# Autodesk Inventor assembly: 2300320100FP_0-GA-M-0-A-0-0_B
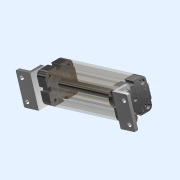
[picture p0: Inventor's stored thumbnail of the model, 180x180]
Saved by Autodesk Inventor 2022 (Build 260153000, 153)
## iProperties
Category: PARTsolutions
Company: METALWORK
Part Number: 2300320100FP_0-GA-M-0-A-0-0_B
Catalog Web Link: www.cadenas.de
Description: Compact cylinder series CMPC TWO-FLAT-
Vendor: METALWORK
Document SubType Name: Assembly
Designer: partserver
Manufacturer: METALWORK
Mass: 243.147 g
Surface Area: 965.542 cm^2
Volume: 243.147 cm^3
PSOL_IDENT_0: {$CADENAS_DATA\23d-libs\metalwork\actuators\comp_cyl_ser_cmpc_2_flat\cmpc_2_flat\cmpc_2_flat_asmtab.
PSOL_IDENT_1: prj},285 {VTYP=3D},{STYP=ASSTAB},{NB=2300320100FP/0-GA-M-0-A-0-0},{LINA=2300320100FP},{NN=Compact cy
PSOL_IDENT_2: linder series CMPC TWO-FLAT},{DATE=18.06.2021 08:06:07},{GEOMDATE=06.02.2018 07:57:17},{VERSION=},{L
PSOL_IDENT_3: INEID=50},{WBVAR=TYPE,VE,EX,HUB,HUBST,MAT,SE,AC1,AC2,AC3,AC4,AC5},{WBNUMERIC=TYPE,HUB,HUBST}  {NB=23
PSOL_IDENT_4: 00320100FP/0-GA-M-0-A-0-0},{LINA=2300320100FP},{KT=DUMMY},{IDNR=},{CODE=2300320100FP},{DI=32},{TYPE=
PSOL_IDENT_5: 23},{VE=0},{EX=0},{HUB=100},{HUBX1=[1:300]},{HUBX2=0100},{HUBST=0},{MAT=F},{SE=P},{VA=25},{VB=0},{VB
PSOL_IDENT_6: A=0},{VC=14},{VOCF=1},{AC1=GA-M},{AC1X= <'0','','blank.jpg'>, 'GA-M','ROD EYE - MODEL GA-M','ga_m.jp
PSOL_IDENT_7: g','GA','COMPENSATION JOINT - MODEL GA','ga.jpg','GK-M','FORK - MODEL GK-M','gk_m.jpg','GA-K','SELF
PSOL_IDENT_8: ALIGNING ROD COUPLER - MODEL GA-K','ga_k.jpg' },{AC2=0},{AC2X= <'0','N/A','blank.jpg'> },{AC3=A},{AC
PSOL_IDENT_9: 3X= <'0','','blank.jpg'>,'A','FOOT - MODEL A','a.jpg','X','FLANGE FOR OPPOSITE CYLINDERS','x.jpg','B'
PSOL_IDENT_10: ,'HINGE - MODEL B','b.jpg','B+GL','HINGE - MODEL B + GL','b_gl.jpg','CF','FRONT FLANGE - MODEL CF','
PSOL_IDENT_11: cf.jpg','CR','REAR FLANGE - MODEL CR','cr.jpg'},{AC3Y=A},{AC4=0},{AC5=0},{AC45X= <'0','','blank.jpg'
PSOL_IDENT_12: >,'W0952025390','HALL N.O. PNP SENSOR, VERTICAL INSERTION 2.5m','sensor.jpg','W0952029394','HALL N.O
PSOL_IDENT_13: . PNP SENSOR, VERTICAL INSERTION 300 mm M8','sensor.jpg','W0952022180','REED N.O. PNP SENSOR, VERTIC
PSOL_IDENT_14: AL INSERTION 2.5m','sensor.jpg' ,'W0952028184','REED N.O. PNP SENSOR, VERTICAL INSERTION 300 mm M8','
PSOL_IDENT_15: sensor.jpg', 'W0952125556','HALL N.O. SENSOR, VERTICAL INSERTION 2m ATEX','sensor.jpg'},{INFO=Catalo
PSOL_IDENT_16: gue},{PPATH=cmpc_2_flat_asmtpl.prj},{A=47},{B=32.25},{B2=},{C=12},{C1=9},{CH=10},{CH1=17},{D=48.5},{
PSOL_IDENT_17: E=6},{F=4},{G=44.5},{H=7.5},{H1=37},{K=30},{L=4},{M=14},{M1X=114},{M1=},{N=59.5},{N2=},{O=M6},{O1=5.
PSOL_IDENT_18: 2},{P=M6},{Q=G1/8},{R=M10x1.25},{S=22},{VER=1},{ACALG3= A},{ACALG2=},{ACALG1= _ GA-M}
NB: 2300320100FP/0-GA-M-0-A-0-0
NN: Compact cylinder series CMPC TWO-FLAT
NBSYN: $CODE./$HUBST.-$AC1.-$AC2.-$AC3.-$AC4.-$AC5.
LINA: 2300320100FP
CATALOG: Metalwork
CODE: 2300320100FP
DI: 32
TYPE: Centre distance to UNITOP, male rod
VE: Double-acting
EX: Standard
HUB: 100
HUBST: 0
MAT: Two-Flat piston rod AISI 303 stainless steel nut
SE: Polyurethane
AC1: ROD EYE - MODEL GA-M
AC2: N/A
AC3: FOOT - MODEL A
INFO: Catalogue
A: 47
B: 32.25
C: 12
C1: 9
CH: 10
CH1: 17
D: 48.5
E: 6
F: 4
G: 44.5
H: 7.5
H1: 37
K: 30
L: 4
M: 14
N: 59.5
O: M6
O1: 5.2
P: M6
Q: G1/8
R: M10x1.25
S: 22
SUPPLIER: METALWORK
ARTICLENO: 2300320100FP/0-GA-M-0-A-0-0
BOMINFO: 2300320100FP
CREATOR: CADENAS GmbH
Title: 2300320100FP
Author: Cadenas PARTsolutions
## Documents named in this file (8)
- C:\Users\admin\Desktop\inventor\sistema_piegatura\2300320100FP_0-GA-M-0-A-0-0_B.iam
- C:\Users\admin\Desktop\inventor\sistema_piegatura\230-32-CMPC2F-HF.ipt
- C:\Users\admin\Desktop\inventor\sistema_piegatura\230-32_100-CMPC2F-BR.ipt
- C:\Users\admin\Desktop\inventor\sistema_piegatura\230-32-CMPC2F-HR.ipt
- C:\Users\admin\Desktop\inventor\sistema_piegatura\W0950322001-25_.ipt
- C:\Users\admin\Desktop\inventor\sistema_piegatura\Cylinder head screw DIN 912 M6x16.ipt
- C:\Users\admin\Desktop\inventor\sistema_piegatura\230-32_100-CMPC2F-PR.ipt
- C:\Users\admin\Desktop\inventor\sistema_piegatura\W0950326021-13.ipt
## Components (11 placed, 7 different names)
1. 230-32-CMPC2F-HF:1 — Coincidente:7, Coincidente:8, Coincidente:9, Coincidente:10, Coincidente:11, Coincidente:12, Coincidente:13
2. 230-32_100-CMPC2F-BR:1 — Coincidente:1, Coincidente:2, Coincidente:3, Coincidente:7, Coincidente:8, Coincidente:9, Angolo:3
3. 230-32-CMPC2F-HR:1 — Coincidente:1, Coincidente:2, Coincidente:3, Coincidente:4, Coincidente:5, Coincidente:6, muovi_2300320100FP_0-GA-M-0-A-0-0
4. W0950322001-25_:1 — Coincidente:4, Coincidente:5, Coincidente:6, Rotazionale:1, Rotazionale:2
5. Cylinder head screw DIN 912 M6x16:1 — Rotazionale:2
6. Cylinder head screw DIN 912 M6x16:2 — Rotazionale:1
7. W0950322001-25_:2 — Coincidente:10, Coincidente:11, Coincidente:12, Rotazionale:3, Rotazionale:4, Angolo:2
8. Cylinder head screw DIN 912 M6x16:3 — Rotazionale:3
9. Cylinder head screw DIN 912 M6x16:4 — Rotazionale:4
10. W0950326021-13:1 — Rotazionale:6, Angolo:3
11. 230-32_100-CMPC2F-PR:1 — Angolo:2, Coincidente:13, muovi_2300320100FP_0-GA-M-0-A-0-0, Rotazionale:6
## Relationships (21: Mate 14, RevoluteJoint 5, Angle 2)
- Coincidente:1 [Mate]: 230-32_100-CMPC2F-BR:1 ↔ 230-32-CMPC2F-HR:1
- Coincidente:2 [Mate]: 230-32_100-CMPC2F-BR:1 ↔ 230-32-CMPC2F-HR:1
- Coincidente:3 [Mate]: 230-32_100-CMPC2F-BR:1 ↔ 230-32-CMPC2F-HR:1
- Coincidente:4 [Mate]: 230-32-CMPC2F-HR:1 ↔ W0950322001-25_:1
- Coincidente:5 [Mate]: 230-32-CMPC2F-HR:1 ↔ W0950322001-25_:1
- Coincidente:6 [Mate]: 230-32-CMPC2F-HR:1 ↔ W0950322001-25_:1
- Rotazionale:1 [RevoluteJoint]: W0950322001-25_:1 ↔ Cylinder head screw DIN 912 M6x16:2
- Rotazionale:2 [RevoluteJoint]: W0950322001-25_:1 ↔ Cylinder head screw DIN 912 M6x16:1
- Coincidente:7 [Mate]: 230-32-CMPC2F-HF:1 ↔ 230-32_100-CMPC2F-BR:1
- Coincidente:8 [Mate]: 230-32-CMPC2F-HF:1 ↔ 230-32_100-CMPC2F-BR:1
- Coincidente:9 [Mate]: 230-32-CMPC2F-HF:1 ↔ 230-32_100-CMPC2F-BR:1
- Coincidente:10 [Mate]: 230-32-CMPC2F-HF:1 ↔ W0950322001-25_:2
- Coincidente:11 [Mate]: 230-32-CMPC2F-HF:1 ↔ W0950322001-25_:2
- Coincidente:12 [Mate]: 230-32-CMPC2F-HF:1 ↔ W0950322001-25_:2
- Rotazionale:3 [RevoluteJoint]: W0950322001-25_:2 ↔ Cylinder head screw DIN 912 M6x16:3
- Rotazionale:4 [RevoluteJoint]: W0950322001-25_:2 ↔ Cylinder head screw DIN 912 M6x16:4
- Angolo:2 [Angle]: W0950322001-25_:2 ↔ 230-32_100-CMPC2F-PR:1
- Coincidente:13 [Mate]: 230-32-CMPC2F-HF:1 ↔ 230-32_100-CMPC2F-PR:1
- muovi_2300320100FP_0-GA-M-0-A-0-0 [Mate]: 230-32-CMPC2F-HR:1 ↔ 230-32_100-CMPC2F-PR:1
- Rotazionale:6 [RevoluteJoint]: W0950326021-13:1 ↔ 230-32_100-CMPC2F-PR:1
- Angolo:3 [Angle]: 230-32_100-CMPC2F-BR:1 ↔ W0950326021-13:1
